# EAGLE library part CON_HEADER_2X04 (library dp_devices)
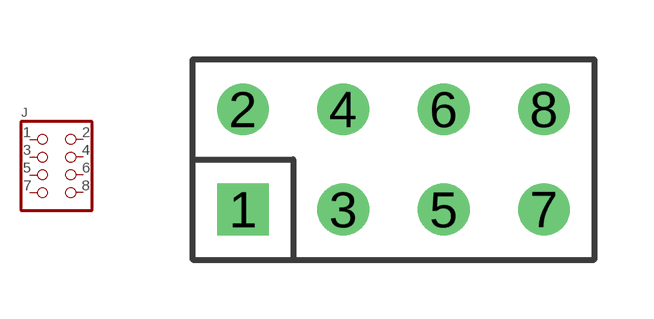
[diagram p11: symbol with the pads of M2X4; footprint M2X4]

Designator prefix J

## CON_HEADER_2X04-PTH  [M2X4]
1  P$1  pas
2  P$2  pas
3  P$3  pas
4  P$4  pas
5  P$5  pas
6  P$6  pas
7  P$7  pas
8  P$8  pas

## Footprint M2X4 (pad centres in mm)
drill 0.8 square: 1 -3.81,-1.27
drill 0.8 round: 2 -3.81,1.27; 3 -1.27,-1.27; 4 -1.27,1.27; 5 1.27,-1.27; 6 1.27,1.27; 7 3.81,-1.27; 8 3.81,1.27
